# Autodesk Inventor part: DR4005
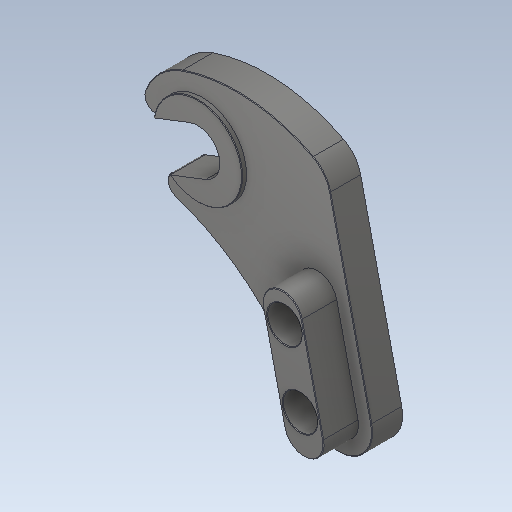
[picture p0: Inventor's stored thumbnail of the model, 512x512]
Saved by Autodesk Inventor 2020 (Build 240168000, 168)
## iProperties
Created: 2015-11
Part Number: DR4005
Material: solidworks materials|7075-T6 (SN)|177
Document SubType Name: Modeling
Designer: Tomasz
Density: 2.81 g/cm^3
Appearance: 0,0,0
Sending System: SolidWorks 2017
Last Author: Tomasz
Last Saved: 2017-09-26
Author: Tomasz
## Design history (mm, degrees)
feature "Imported1"
node "Bryła1"
